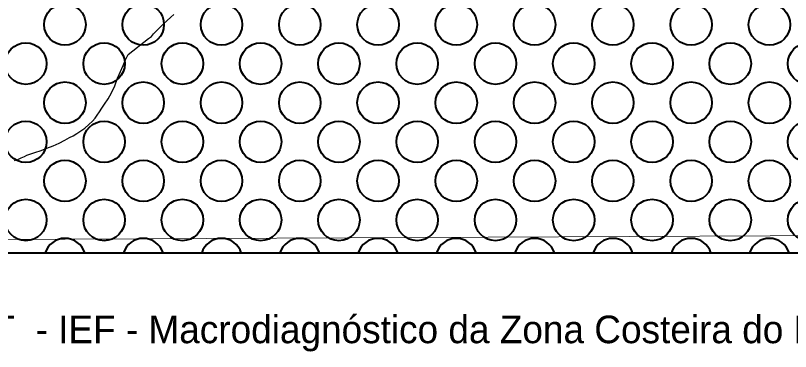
# Model space of a CAD drawing. Extents: x -10.5 to 30.8, y 18.4 to 58.7.
# Drawn here: x -2.95 to 4.05, y 20.84 to 23.88 of the extents above; entities that cross this region are included whole.
import ezdxf

# ---------------------------------------------------------------- set-up
doc = ezdxf.new("R2010")
doc.units = 0
doc.header["$LTSCALE"] = 0.08
doc.linetypes.add('DASH_DOUBLE_DOT', pattern=[9.2, 5, -1.2, 0.3, -1.2, 0.3, -1.2])
for name, color, linetype, lineweight in [('19', 7, 'DASH_DOUBLE_DOT', 53), ('44', 7, 'Continuous', 35), ('52', 7, 'Continuous', 13), ('58', 7, 'Continuous', 13), ('6', 7, 'Continuous', 40), ('60', 7, 'Continuous', 13), ('8', 7, 'Continuous', 25)]:
    doc.layers.add(name, color=color, linetype=linetype, lineweight=lineweight)

msp = doc.modelspace()

# ---------------------------------------------------------------- linework, layer by layer
at = {"layer": '19'}
msp.add_arc((-0.44301, 2.34427), 22.39632, 64.89153, 85.66215, dxfattribs=at)
at = {"layer": '44'}
msp.add_lwpolyline([(-6.64608, 21.84641), (-6.71324, 21.73), (30.62637, 21.73), (30.75566, 58.74412)], dxfattribs=at)
at = {"layer": '52'}
msp.add_lwpolyline([(-10.15205, 21.8176), (10.23286, 21.91268), (15.32232, 21.9365), (25.50135, 21.93423), (29.65751, 21.91292)], dxfattribs=at)
at = {"layer": '6'}
for p, q in [((-2.68657, 21.73), (-2.32893, 21.73)), ((-1.97946, 21.73), (-1.62182, 21.73)), ((-1.27235, 21.73), (-0.91472, 21.73)), ((-0.56525, 21.73), (-0.20761, 21.73)), ((0.14186, 21.73), (0.4995, 21.73)), ((0.84897, 21.73), (1.2066, 21.73)), ((1.55607, 21.73), (1.91371, 21.73)), ((2.26318, 21.73), (2.62082, 21.73)), ((2.97029, 21.73), (3.32792, 21.73)), ((3.67739, 21.73), (4.03503, 21.73))]:
    msp.add_line(p, q, dxfattribs=at)
at = {"layer": '6', "lineweight": 25}
msp.add_lwpolyline([(7.28557, 21.73), (-10.13305, 21.73), (-10.13304, 28.05258)], dxfattribs=at)
at = {"layer": '6'}
for centre in [(-2.50775, 23.79493), (-1.80064, 23.79493), (-1.09353, 23.79493), (-0.38643, 23.79493), (0.32068, 23.79493), (1.02779, 23.79493), (1.73489, 23.79493), (2.442, 23.79493), (3.14911, 23.79493), (3.85621, 23.79493), (-2.8613, 23.44138), (-2.1542, 23.44138), (-1.44709, 23.44138), (-0.73998, 23.44138), (-0.03287, 23.44138), (0.67423, 23.44138), (1.38134, 23.44138), (2.08845, 23.44138), (2.79555, 23.44138), (3.50266, 23.44138), (4.20977, 23.44138), (-2.50775, 23.08782), (-1.80064, 23.08782), (-1.09353, 23.08782), (-0.38643, 23.08782), (0.32068, 23.08782), (1.02779, 23.08782), (1.73489, 23.08782), (2.442, 23.08782), (3.14911, 23.08782), (3.85621, 23.08782), (-2.8613, 22.73427), (-2.1542, 22.73427), (-1.44709, 22.73427), (-0.73998, 22.73427), (-0.03287, 22.73427), (0.67423, 22.73427), (1.38134, 22.73427), (2.08845, 22.73427), (2.79555, 22.73427), (3.50266, 22.73427), (4.20977, 22.73427), (-2.50775, 22.38072), (-1.80064, 22.38072), (-1.09353, 22.38072), (-0.38643, 22.38072), (0.32068, 22.38072), (1.02779, 22.38072), (1.73489, 22.38072), (2.442, 22.38072), (3.14911, 22.38072), (3.85621, 22.38072), (-2.8613, 22.02716), (-2.1542, 22.02716), (-1.44709, 22.02716), (-0.73998, 22.02716), (-0.03287, 22.02716), (0.67423, 22.02716), (1.38134, 22.02716), (2.08845, 22.02716), (2.79555, 22.02716), (3.50266, 22.02716), (4.20977, 22.02716)]:
    msp.add_circle(centre, 0.1875, dxfattribs=at)
for centre, start, end in [((-2.50775, 21.67361), 17.50423, 162.49576), ((-1.80064, 21.67361), 17.50421, 162.49578), ((-1.09353, 21.67361), 17.50419, 162.4958), ((-0.38643, 21.67361), 17.50417, 162.49582), ((0.32068, 21.67361), 17.50416, 162.49583), ((1.02779, 21.67361), 17.50414, 162.49585), ((1.73489, 21.67361), 17.50412, 162.49587), ((2.442, 21.67361), 17.50411, 162.49589), ((3.14911, 21.67361), 17.50409, 162.4959), ((3.85621, 21.67361), 17.50407, 162.49592)]:
    msp.add_arc(centre, 0.1875, start, end, dxfattribs=at)
at = {"layer": '60', "lineweight": 40}
msp.add_line((-10.13305, 21.73), (30.62637, 21.73), dxfattribs=at)
at = {"layer": '8'}
for points in [[(-1.72697, 23.68594), (-1.70691, 23.7124), (-1.67733, 23.7405), (-1.64778, 23.7711), (-1.61824, 23.8017), (-1.58614, 23.82984), (-1.55158, 23.86054), (-1.52445, 23.88609)], [(-2.5615, 22.72081), (-2.50908, 22.74885), (-2.46663, 22.77178), (-2.43418, 22.78962), (-2.40175, 22.80995), (-2.36433, 22.83283), (-2.32943, 22.85819), (-2.29209, 22.89108), (-2.25975, 22.92142), (-2.23492, 22.94918), (-2.21757, 22.97437), (-2.19526, 23.00461), (-2.17548, 23.03733), (-2.15072, 23.07509), (-2.11853, 23.12294), (-2.08642, 23.17829), (-2.05686, 23.24112), (-2.03236, 23.3089), (-2.00531, 23.36921), (-1.98321, 23.42446), (-1.9611, 23.47721), (-1.93644, 23.52498), (-1.75347, 23.66747), (-1.72697, 23.68594)], [(-2.96397, 22.56423), (-2.93397, 22.57453), (-2.90398, 22.58984), (-2.87398, 22.60014), (-2.85151, 22.61287), (-2.82402, 22.62315), (-2.779, 22.63861), (-2.72398, 22.65667), (-2.67149, 22.6772), (-2.61398, 22.69778), (-2.5615, 22.72081)]]:
    msp.add_lwpolyline(points, dxfattribs=at)

# ---------------------------------------------------------------- texts
at = {"layer": '58'}
msp.add_text('FONTE: PROJETO REMAC,1979 - OCEANSAT  - IEF - Macrodiagnóstico da Zona Costeira do Brasil na Escala da União/MMA', height=0.2497, dxfattribs=at).set_placement((-10.12086, 20.91268))

doc.saveas('drawing.dxf')
